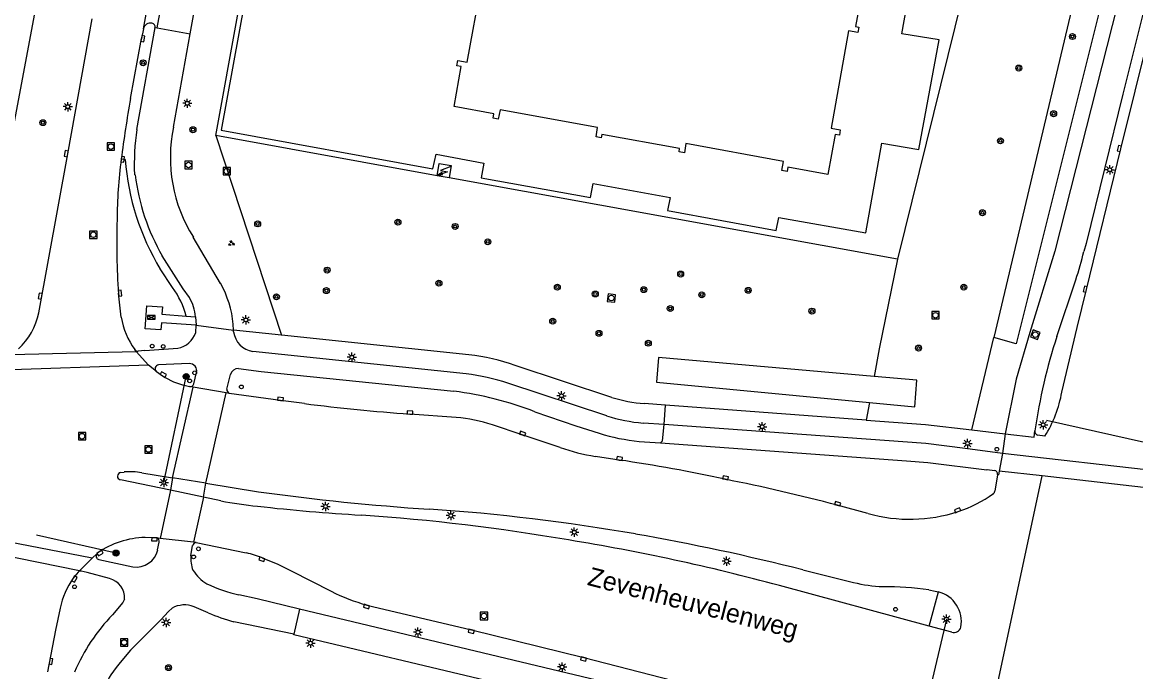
# Model space of a CAD drawing. Extents: x 130998 to 133001, y 398999 to 403002.
# Drawn here: x 132704.3 to 132854, y 399481.4 to 399568.7 of the extents above; entities that cross this region are included whole.
import ezdxf

# ---------------------------------------------------------------- set-up
doc = ezdxf.new("R2010")
doc.units = 0
for name, color, linetype in [('gg-afsc-hekwerk', 7, 'Continuous'), ('gg-anno-openbare ruimte label', 7, 'Continuous'), ('gg-bbg-hoofdgebouw', 7, 'Continuous'), ('gg-bbg-lage trafo', 7, 'Continuous'), ('gg-knt-verharding', 7, 'Continuous'), ('gg-knt-verharding nz', 7, 'Continuous'), ('gt-grn-groengrens', 7, 'Continuous'), ('gt-grn-weggrens', 7, 'Continuous'), ('gt-knt-lijn portaal', 7, 'Continuous'), ('gt-symb-boom', 7, 'Continuous'), ('gt-symb-drukknoppaal', 7, 'Continuous'), ('gt-symb-groenvak', 7, 'Continuous'), ('gt-symb-kolk', 7, 'Continuous'), ('gt-symb-lichtmast', 7, 'Continuous'), ('gt-symb-portaalmast', 7, 'Continuous'), ('gt-symb-rioolschacht', 7, 'Continuous'), ('gt-symb-trafo symbool', 7, 'Continuous'), ('gt-symb-verkeersregelinstallatiekast', 7, 'Continuous'), ('gt-symb-verkeersregelinstallatiepaal', 7, 'Continuous')]:
    doc.layers.add(name, color=color, linetype=linetype)

# ---------------------------------------------------------------- blocks, each defined once
blk = doc.blocks.new('gt0-KOLK')
at = {"layer": 'gt-symb-kolk'}
blk.add_lwpolyline([(0, 0), (0.37, 0), (0.37, 0.4), (-0.38, 0.4), (-0.38, 0), (0, 0)], dxfattribs=at)
blk = doc.blocks.new('gt0-VIPAAL')
at = {"layer": 'gt-symb-verkeersregelinstallatiepaal'}
blk.add_circle((0, 0), 0.25, dxfattribs=at)
blk = doc.blocks.new('gt0-PORTM')
at = {"layer": 'gt-symb-portaalmast'}
for radius in [0.4, 0.33, 0.27, 0.21, 0.15]:
    blk.add_circle((0, 0), radius, dxfattribs=at)
blk = doc.blocks.new('gt0-DPAAL')
at = {"layer": 'gt-symb-drukknoppaal'}
blk.add_circle((0, 0), 0.25, dxfattribs=at)
blk = doc.blocks.new('gt0-BOOM')
at = {"layer": 'gt-symb-boom'}
for radius in [0.4, 0.2]:
    blk.add_circle((0, 0), radius, dxfattribs=at)
blk = doc.blocks.new('gt0-LMAST')
at = {"layer": 'gt-symb-lichtmast'}
for p, q in [((-0.18, 0.17), (-0.45, 0.44)), ((-0.01, 0.25), (-0.01, 0.62)), ((0.17, 0.17), (0.44, 0.44)), ((-0.26, 0), (-0.63, 0)), ((-0.18, -0.18), (-0.45, -0.45)), ((-0.01, -0.25), (-0.01, -0.63)), ((0.44, -0.45), (0.17, -0.18)), ((0.24, 0), (0.62, 0))]:
    blk.add_line(p, q, dxfattribs=at)
blk.add_circle((-0.01, 0), 0.25, dxfattribs=at)
blk = doc.blocks.new('gt0-VRIKST')
at = {"layer": 'gt-symb-verkeersregelinstallatiekast'}
for p, q in [((-0.5, -0.25), (0.5, 0.25)), ((-0.5, 0.25), (0.5, -0.25))]:
    blk.add_line(p, q, dxfattribs=at)
blk.add_lwpolyline([(0.5, 0.25), (-0.5, 0.25), (-0.5, -0.25), (0.5, -0.25)], close=True, dxfattribs=at)
blk = doc.blocks.new('gt0-GRVAK')
at = {"layer": 'gt-symb-groenvak'}
for p, q in [((-0.11, 0.19), (-0.23, 0.24)), ((-0.18, 0.15), (0.09, 0.15)), ((-0.09, 0.21), (-0.16, 0.32)), ((-0.05, 0.21), (-0.05, 0.39)), ((0, 0.21), (0.06, 0.32)), ((0.01, 0.19), (0.13, 0.24)), ((0.26, -0.05), (0.2, 0.06)), ((0.3, -0.05), (0.3, 0.13)), ((0.35, -0.05), (0.41, 0.06)), ((-0.24, -0.23), (-0.36, -0.18)), ((-0.32, -0.26), (-0.05, -0.26)), ((-0.23, -0.21), (-0.29, -0.09)), ((-0.18, -0.2), (-0.18, -0.02)), ((-0.14, -0.21), (-0.07, -0.09)), ((-0.12, -0.23), (0, -0.18)), ((0.24, -0.07), (0.12, -0.02)), ((0.17, -0.11), (0.44, -0.11)), ((0.37, -0.07), (0.49, -0.02))]:
    blk.add_line(p, q, dxfattribs=at)
blk = doc.blocks.new('gt0-RS')
at = {"layer": 'gt-symb-rioolschacht'}
blk.add_lwpolyline([(-0.5, -0.5), (0.5, -0.5), (0.5, 0.5), (-0.5, 0.5)], close=True, dxfattribs=at)
blk.add_circle((0, 0), 0.375, dxfattribs=at)
blk = doc.blocks.new('gt0-HSP')
at = {"layer": 'gt-symb-trafo symbool'}
for points in [[(0.77, 0.75), (-0.53, 0), (0.47, 0), (-0.83, -0.75)], [(-0.22, -0.24), (-0.83, -0.75), (-0.08, -0.48)]]:
    blk.add_lwpolyline(points, dxfattribs=at)

msp = doc.modelspace()

# ---------------------------------------------------------------- linework, layer by layer
at = {"layer": 'gg-afsc-hekwerk'}
for p, q in [((132844.01, 399625.98), (132821.97, 399536.85)), ((132697.6, 399525.33), (132706.9, 399574.84)), ((132730.31, 399553.47), (132733.34, 399569.98)), ((132760.05, 399548.02), (132730.31, 399553.47)), ((132821.97, 399536.85), (132761.69, 399547.77))]:
    msp.add_line(p, q, dxfattribs=at)
at = {"layer": 'gg-bbg-hoofdgebouw'}
msp.add_lwpolyline([(132818.22, 399578.57), (132816.33, 399568.11), (132816.77, 399568.01), (132816.64, 399567.3), (132815.39, 399567.51), (132813.03, 399554.43), (132814.26, 399554.21), (132814.15, 399553.5), (132813.58, 399553.58), (132812.6, 399548.22), (132807.23, 399549.21), (132807.13, 399548.63), (132806.43, 399548.75), (132806.65, 399549.97), (132793.52, 399552.38), (132793.32, 399551.13), (132792.6, 399551.24), (132792.67, 399551.7), (132782.2, 399553.6), (132782.12, 399553.16), (132781.43, 399553.28), (132781.63, 399554.52), (132768.52, 399556.9), (132768.29, 399555.65), (132767.59, 399555.78), (132767.69, 399556.36), (132762.34, 399557.35), (132763.28, 399562.71), (132762.71, 399562.8), (132762.85, 399563.52), (132764.12, 399563.29), (132766.02, 399573.84)], dxfattribs=at)
at = {"layer": 'gg-bbg-lage trafo'}
msp.add_line((132761.69, 399547.77), (132760.05, 399548.02), dxfattribs=at)
msp.add_lwpolyline([(132760.05, 399548.02), (132760.32, 399549.68), (132761.96, 399549.41), (132761.69, 399547.77)], dxfattribs=at)
at = {"layer": 'gg-knt-verharding'}
for p, q in [((132720.58, 399567.79), (132724.07, 399586.98)), ((132722.42, 399567.92), (132725.76, 399586.22)), ((132726.88, 399567.12), (132727.67, 399571.55)), ((132719.69, 399554.27), (132722.14, 399567.96)), ((132720.58, 399567.79), (132720.31, 399566.5)), ((132722.14, 399567.96), (132722.42, 399567.92)), ((132718.83, 399558.43), (132720.31, 399566.5)), ((132724.64, 399554.56), (132726.88, 399567.12)), ((132719.47, 399548.18), (132719.37, 399548.2)), ((132730.96, 399533.58), (132727.29, 399539.79)), ((132843.4, 399526.44), (132845.92, 399534.07)), ((132717.58, 399529.02), (132717.22, 399532.24)), ((132726.34, 399529.16), (132727.57, 399529.08)), ((132727.57, 399529.08), (132727.65, 399527.95)), ((132727.62, 399526.98), (132727.65, 399527.95)), ((132732.69, 399527.28), (132732.65, 399528.08)), ((132739.15, 399526.61), (132732.69, 399527.28)), ((132732.71, 399527.06), (132732.69, 399527.28)), ((132764.34, 399523.96), (132739.15, 399526.61)), ((132720.76, 399524.54), (132719.86, 399524.47)), ((132720.76, 399524.54), (132725.19, 399524.86)), ((132763.98, 399521.41), (132735.27, 399524.43)), ((132726.72, 399522.79), (132722.62, 399522.62)), ((132783.54, 399518.25), (132770.56, 399522.55)), ((132722.32, 399521.74), (132723.16, 399521.16)), ((132727.35, 399520.06), (132727.72, 399521.58)), ((132731.8, 399519.37), (132732.27, 399521.33)), ((132726.25, 399519.85), (132726.79, 399519.7)), ((132782.86, 399515.77), (132769.59, 399520.17)), ((132790.77, 399517.2), (132787.92, 399517.41)), ((132817.75, 399515.19), (132790.77, 399517.2)), ((132762.63, 399515.56), (132756.41, 399516.01)), ((132817.75, 399515.19), (132825.74, 399514.61)), ((132790.57, 399514.61), (132787.77, 399514.79)), ((132825.74, 399514.61), (132831.96, 399513.88)), ((132831.96, 399513.88), (132836.43, 399513.35)), ((132836.43, 399513.35), (132836.08, 399510.69)), ((132787.24, 399512.34), (132790.08, 399512.13)), ((132841.77, 399513.04), (132840.79, 399513.15)), ((132836.08, 399510.69), (132831.07, 399511.36)), ((132836.08, 399510.69), (132835.64, 399508.35)), ((132784.56, 399509.83), (132781.35, 399510.32)), ((132717.5, 399508.16), (132717.99, 399508.22)), ((132720.36, 399508.11), (132724.48, 399507.44)), ((132724.48, 399507.44), (132724.2, 399505.79)), ((132835.4, 399507.86), (132835.04, 399505.65)), ((132724.2, 399505.79), (132717.48, 399507.18)), ((132728.64, 399504.83), (132728.96, 399506.7)), ((132728.96, 399506.7), (132736.06, 399505.57)), ((132730.99, 399504.35), (132728.64, 399504.83)), ((132817.99, 399502.64), (132813.87, 399503.75)), ((132722.49, 399497.76), (132722.71, 399498.79)), ((132727.69, 399498.73), (132734.41, 399497.34)), ((132726.96, 399496.96), (132727.2, 399498.32)), ((132714.6, 399496.44), (132719.15, 399495.48)), ((132711.82, 399494.77), (132711.14, 399493.93)), ((132809.24, 399495.07), (132816.05, 399493.37)), ((132826.21, 399487.49), (132806.1, 399492.96)), ((132826.21, 399487.49), (132827.45, 399492.12)), ((132729.29, 399489.29), (132727.39, 399490.09)), ((132741.56, 399489.79), (132740.82, 399486.41)), ((132792.11, 399477.72), (132741.56, 399489.79)), ((132740.82, 399486.41), (132732.74, 399488.1)), ((132829.25, 399486.69), (132826.21, 399487.49))]:
    msp.add_line(p, q, dxfattribs=at)
for points in [[(132901.43, 399740.52), (132890.59, 399708.5), (132889.85, 399706.06), (132889.16, 399703.6), (132885.94, 399691.45), (132873.35, 399642.43), (132865.28, 399610.8), (132857.35, 399579.47), (132852.24, 399559.02), (132847.33, 399538.95), (132847.01, 399537.87)], [(132869.85, 399643.31), (132858.59, 399599.11), (132850.82, 399568.23), (132843.11, 399537.92), (132839.74, 399526.96), (132837.9, 399520.68), (132836.43, 399513.35)], [(132844.07, 399518.96), (132846.11, 399527.65), (132847.38, 399532.75), (132851.98, 399551.67), (132857.77, 399574.97), (132861.41, 399589.44), (132866.24, 399608.29), (132874.84, 399642.05)], [(132734.18, 399571.34), (132731.05, 399554.17), (132759.51, 399548.97), (132759.93, 399550.94), (132766.33, 399549.73), (132765.98, 399547.78), (132780.7, 399545.1), (132781.03, 399546.99), (132791.38, 399545.11), (132791.03, 399543.38), (132805.64, 399540.69), (132806, 399542.45), (132817.69, 399540.35), (132819.86, 399552.42), (132824.83, 399551.56), (132827.55, 399566.29), (132822.54, 399567.14), (132824.39, 399577.39), (132830.94, 399576.21), (132833.57, 399590.79), (132827.01, 399592.03), (132829.12, 399603.48), (132837.22, 399602.02), (132842.25, 399629.36)], [(132706.51, 399529.62), (132710.4, 399550.98), (132713.71, 399569.15)], [(132726.76, 399531.67), (132725.94, 399532.83), (132723.11, 399537.28)], [(132727.65, 399527.95), (132723, 399528.29), (132722.92, 399527.31), (132720.81, 399527.45), (132721.02, 399530.55), (132723.14, 399530.41), (132723.06, 399529.42), (132726.34, 399529.16)], [(132733.36, 399522.12), (132736.43, 399521.73), (132762.32, 399519.08)], [(132742.22, 399517.42), (132739, 399517.82), (132732.12, 399518.79)], [(132773.22, 399516.32), (132778.72, 399514.41), (132781.86, 399513.42)], [(132776.59, 399511.51), (132771.5, 399513.2), (132767.49, 399514.54)], [(132790.08, 399512.13), (132790.38, 399512.41), (132790.57, 399514.61)], [(132831.07, 399511.36), (132825.75, 399512.03), (132790.57, 399514.61)], [(132790.08, 399512.13), (132823.16, 399509.74), (132826.06, 399509.51), (132833.98, 399508.51), (132834, 399508.57), (132835.01, 399508.43)], [(132835.64, 399508.35), (132835.55, 399507.85), (132835.4, 399507.86)], [(132722.33, 399499.35), (132722.06, 399499.37), (132720.8, 399499.42)], [(132714.41, 399497.33), (132714.36, 399497.29), (132714.31, 399497.23)], [(132736.56, 399496.69), (132738.65, 399495.82), (132740.46, 399494.94), (132745.81, 399492.19)], [(132716.04, 399493.89), (132713.03, 399494.73), (132712.23, 399494.89)], [(132718.05, 399491.14), (132717.83, 399490.7), (132716.44, 399489.04)], [(132741.56, 399489.79), (132735.89, 399491.19), (132733.42, 399491.71)], [(132826.16, 399492.37), (132827.01, 399492.22), (132827.45, 399492.12)], [(132709.4, 399489.92), (132708.75, 399486.97), (132707.7, 399481.36)], [(132724.43, 399489.91), (132723.95, 399489.47), (132722.91, 399488.35), (132718.84, 399484.27), (132717.45, 399482.63), (132716.91, 399481.95), (132716.21, 399480.97), (132715.97, 399480.58), (132715.62, 399479.84), (132715.24, 399478.88)], [(132750.63, 399490.33), (132764.7, 399487), (132779.79, 399483.29), (132794.75, 399479.44), (132808.74, 399475.76), (132812.85, 399474.65)], [(132767.55, 399479.99), (132740.8, 399486.33), (132740.82, 399486.41)]]:
    msp.add_lwpolyline(points, dxfattribs=at)
for centre, radius, start, end in [((132721.55, 399567.58), 0.992, 79.6332, 167.8621), ((132721.65, 399568.06), 0.497, 347.8024, 80.7236), ((132902.23, 399526.52), 186.15, 170.1311, 172.6692), ((132750.49, 399549.61), 31.14, 171.3902, 182.5961), ((132744.06, 399550.43), 19.86, 167.9729, 212.4033), ((132782.18, 399541.7), 65.15, 172.4405, 179.6426), ((132747.85, 399551.58), 28.58, 186.8446, 210.0379), ((132817.66, 399539.11), 100.67, 178.2926, 183.9131), ((132800.95, 399549.03), 47.4, 341.5976, 346.3803), ((132718.95, 399526.88), 13.75, 5.0182, 29.1755), ((132721.58, 399528.61), 6.02, 4.4418, 30.548), ((132697.54, 399531.47), 9.16, 312.9973, 348.3657), ((132728.16, 399530.97), 10.76, 190.408, 215.7017), ((132724.6, 399527.97), 3.17, 280.6759, 341.6658), ((132735.71, 399527.42), 3.02, 186.8065, 261.738), ((132916.41, 399502.63), 76.8, 161.9353, 171.6577), ((132719.87, 399525.03), 0.564, 217.7168, 268.943), ((132761.89, 399498.77), 25.31, 69.9685, 84.4437), ((132722.65, 399522.11), 0.506, 93.8371, 228.1277), ((132726.78, 399521.82), 0.97, 345.6842, 93.2707), ((132728.33, 399529.06), 9.45, 236.8087, 257.2387), ((132733.31, 399521.04), 1.08, 87.6142, 164.7419), ((132760.47, 399492.05), 29.56, 72.0242, 83.182), ((132726.86, 399520.21), 0.516, 261.8628, 342.5663), ((132732.34, 399519.29), 0.541, 170.8562, 245.8513), ((132756.58, 399473.5), 45.93, 68.76, 82.8215), ((132789.49, 399537.49), 20.14, 252.8133, 265.5292), ((132827.38, 399522.03), 16.96, 338.793, 349.5634), ((132775.14, 399777.06), 261.72, 262.7749, 265.8959), ((132760.78, 399494.69), 20.96, 71.3237, 84.9441), ((132789.88, 399538.24), 23.54, 252.6376, 264.8636), ((132827.38, 399522.01), 16.96, 328.0877, 338.8627), ((132789.86, 399539.17), 26.96, 252.7255, 264.409), ((132841.03, 399513.7), 0.601, 173.8714, 246.3979), ((132785.81, 399538.37), 28.4, 251.0514, 260.9724), ((132754.48, 399304.02), 208, 77.6998, 81.6848), ((132717.59, 399507.66), 0.502, 100.5491, 256.5342), ((132718.76, 399499.62), 8.64, 79.3806, 95.1529), ((132834.93, 399507.95), 0.486, 350.1383, 80.0644), ((132751.3, 399267.65), 244.25, 75.1565, 78.7877), ((132780.08, 399823.82), 321.29, 262.124, 266.2368), ((132824.29, 399520.1), 18.16, 288.7308, 305.5385), ((132834.64, 399505.66), 0.393, 300.542, 359.1169), ((132742.6, 399565.93), 62.67, 259.3234, 263.8907), ((132765.19, 399764.27), 262.29, 263.5963, 266.6563), ((132740.31, 399231.68), 272.2, 80.1799, 86.0635), ((132823.63, 399522.71), 20.84, 254.3095, 288.1466), ((132730.84, 399225.81), 277.27, 80.2681, 86.0607), ((132733.65, 399196.61), 307.88, 75.7866, 80.0715), ((132721.07, 399487.77), 11.65, 91.2863, 124.8291), ((132722.22, 399498.86), 0.501, 351.9297, 77.5032), ((132727.67, 399498.25), 0.475, 87.1196, 172.1255), ((132733.76, 399226.96), 275.65, 74.7878, 80.8262), ((132714.71, 399496.93), 0.498, 142.7091, 257.187), ((132719.62, 399498.39), 2.95, 260.8133, 347.5956), ((132730.98, 399496.55), 4.04, 174.2479, 202.1621), ((132730.28, 399479.7), 18.12, 69.7064, 76.8021), ((132719.81, 399487.79), 10.63, 144.7121, 168.4465), ((132712.15, 399494.41), 0.482, 79.8466, 132.9924), ((132715.4, 399491.32), 2.65, 356.1407, 76.1214), ((132732.28, 399498.21), 5.96, 212.2722, 237.7278), ((132739.7, 399517.4), 26.45, 246.3684, 256.2694), ((132820.88, 399512.82), 20.03, 256.0382, 267.5114), ((132820.39, 399453.82), 38.98, 81.4932, 90.5569), ((132758.3, 399517.36), 28.1, 243.6116, 254.154), ((132826.37, 399488.08), 4.18, 350.0852, 75.0425), ((132726.09, 399487.03), 3.32, 67.0665, 119.9872), ((132735.01, 399471.18), 25.77, 136.1165, 156.7921), ((132739.59, 399513.56), 26.37, 247.0096, 254.9495), ((132829.55, 399487.62), 0.977, 252.4702, 344.6662)]:
    msp.add_arc(centre, radius, start, end, dxfattribs=at)
at = {"layer": 'gg-knt-verharding nz'}
for p, q in [((132702.76, 399524.02), (132719.59, 399524.43)), ((132719.59, 399524.43), (132719.43, 399524.69)), ((132721.26, 399522.58), (132719.59, 399524.43)), ((132722.32, 399521.74), (132721.26, 399522.58)), ((132724.48, 399507.44), (132727.25, 399519.62)), ((132727.25, 399519.62), (132726.79, 399519.7)), ((132731.69, 399518.87), (132727.25, 399519.62)), ((132728.96, 399506.7), (132731.69, 399518.87)), ((132732.12, 399518.79), (132731.69, 399518.87)), ((132857.61, 399508.28), (132836.08, 399510.69)), ((132728.96, 399506.7), (132724.48, 399507.44)), ((132841.4, 399507.69), (132835.64, 399508.35)), ((132857.86, 399505.8), (132841.4, 399507.69)), ((132724.2, 399505.79), (132722.82, 399499.29)), ((132728.64, 399504.83), (132724.2, 399505.79)), ((132728.64, 399504.83), (132727.3, 399498.77)), ((132713.69, 399496.62), (132700.92, 399499.12)), ((132722.82, 399499.29), (132722.33, 399499.35)), ((132727.3, 399498.77), (132722.82, 399499.29)), ((132727.69, 399498.73), (132727.3, 399498.77)), ((132711.99, 399494.93), (132700.57, 399497.25)), ((132714.31, 399497.23), (132713.69, 399496.62)), ((132713.69, 399496.62), (132711.99, 399494.93)), ((132711.99, 399494.93), (132711.82, 399494.77))]:
    msp.add_line(p, q, dxfattribs=at)
msp.add_lwpolyline([(132721.26, 399522.58), (132700.2, 399521.88), (132699.24, 399522.05)], dxfattribs=at)
at = {"layer": 'gt-grn-groengrens'}
for p, q in [((132730.31, 399553.47), (132739.15, 399526.61)), ((132718.13, 399550.23), (132717.6, 399550.27)), ((132724.51, 399533.02), (132722.83, 399535.51)), ((132831.96, 399513.88), (132834.91, 399526.3)), ((132818.19, 399517.55), (132817.75, 399515.19))]:
    msp.add_line(p, q, dxfattribs=at)
for points in [[(132889.34, 399742.98), (132850.51, 399592.1), (132834.91, 399526.3)], [(132867.67, 399643.86), (132854.6, 399592.15), (132837.93, 399525.45), (132834.91, 399526.3)], [(132821.97, 399536.85), (132819.51, 399524.77), (132818.82, 399521.06)], [(132818.82, 399521.06), (132789.85, 399523.59), (132789.58, 399520.28), (132818.19, 399517.55)], [(132818.19, 399517.55), (132824.29, 399516.97), (132824.57, 399520.55), (132818.82, 399521.06)]]:
    msp.add_lwpolyline(points, dxfattribs=at)
for centre, radius, start, end in [((132751.66, 399552.84), 33.64, 184.4477, 211.0157), ((132715.03, 399526.16), 11.7, 14.8716, 35.8655)]:
    msp.add_arc(centre, radius, start, end, dxfattribs=at)
at = {"layer": 'gt-grn-weggrens'}
for p, q in [((132722.42, 399567.92), (132726.88, 399567.12)), ((132727.65, 399527.95), (132732.69, 399527.28)), ((132790.57, 399514.61), (132790.77, 399517.2)), ((132831.72, 399462.47), (132841.4, 399507.69))]:
    msp.add_line(p, q, dxfattribs=at)
msp.add_lwpolyline([(132836.43, 399513.35), (132840.33, 399512.92), (132840.43, 399513.77)], dxfattribs=at)
at = {"layer": 'gt-knt-lijn portaal'}
for p, q in [((132723.32, 399506.82), (132726.33, 399521.06)), ((132842, 399515.18), (132859.33, 399511.28)), ((132716.9, 399497.33), (132706.22, 399499.74)), ((132828.54, 399488.43), (132823.16, 399465.61))]:
    msp.add_line(p, q, dxfattribs=at)

# ---------------------------------------------------------------- block references
at = {"layer": 'gt-symb-boom'}
for p in [(132845.48, 399566.75), (132720.54, 399563.23), (132838.27, 399562.52), (132842.95, 399556.38), (132707.06, 399555.18), (132727.24, 399554.23), (132835.8, 399552.74), (132833.38, 399543.07), (132735.94, 399541.57), (132754.8, 399541.81), (132762.48, 399541.23), (132766.88, 399539.16), (132745.28, 399535.36), (132792.81, 399534.83), (132745.18, 399532.6), (132760.31, 399533.61), (132776.23, 399533.07), (132787.85, 399532.73), (132801.89, 399532.64), (132830.87, 399533.07), (132738.46, 399531.77), (132781.33, 399532.15), (132795.65, 399532.03), (132791.41, 399530.19), (132810.46, 399529.85), (132775.61, 399528.5), (132781.83, 399526.86), (132788.46, 399525.53), (132824.79, 399524.88), (132723.96, 399481.92)]:
    msp.add_blockref('gt0-BOOM', p, dxfattribs=at)
at = {"layer": 'gt-symb-drukknoppaal'}
for p in [(132723.24, 399525.1), (132727.47, 399521.55), (132835.33, 399511.28), (132727.33, 399496.81)]:
    msp.add_blockref('gt0-DPAAL', p, dxfattribs=at)
at = {"layer": 'gt-symb-groenvak', "rotation": -10.30997039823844}
msp.add_blockref('gt0-GRVAK', (132732.39, 399538.94), dxfattribs=at)
at = {"layer": 'gt-symb-kolk'}
for p, rotation in [((132720.31, 399566.5), -100.38568294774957), ((132710.4, 399550.98), 79.65545752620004), ((132851.98, 399551.67), 76.0609856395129), ((132717.6, 399550.27), -95.941846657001), ((132847.38, 399532.75), 76.29711003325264), ((132706.91, 399531.84), 79.68721352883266), ((132717.22, 399532.24), -83.6277257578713), ((132723.16, 399521.16), -28.456529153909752), ((132739, 399517.82), -7.185074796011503), ((132756.41, 399516.01), -4.135059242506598), ((132771.5, 399513.2), -18.340523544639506), ((132784.56, 399509.83), -9.337616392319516), ((132798.79, 399507.24), -12.155063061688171), ((132813.87, 399503.75), -15.14611614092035), ((132830.12, 399502.9), 23.138193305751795), ((132722.06, 399499.37), 178.0306279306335), ((132714.64, 399497.47), -149.34624659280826), ((132736.56, 399496.69), 160.98833601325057), ((132711.14, 399493.93), -120.01013764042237), ((132750.63, 399490.33), 161.93252307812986), ((132764.7, 399487), 166.69386138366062), ((132707.96, 399482.8), -100.40301367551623), ((132779.79, 399483.29), 166.18882846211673)]:
    msp.add_blockref('gt0-KOLK', p, dxfattribs=dict(at, rotation=rotation))
at = {"layer": 'gt-symb-lichtmast'}
for p in [(132726.49, 399557.78), (132710.41, 399557.33), (132850.5, 399548.85), (132734.37, 399528.66), (132748.6, 399523.65), (132776.8, 399518.47), (132803.78, 399514.31), (132841.54, 399514.57), (132831.39, 399512.06), (132723.32, 399506.82), (132745.08, 399503.59), (132761.92, 399502.37), (132778.52, 399500.13), (132799, 399496.23), (132723.66, 399487.99), (132828.54, 399488.43), (132757.5, 399486.68), (132743.04, 399485.21), (132776.87, 399482.01)]:
    msp.add_blockref('gt0-LMAST', p, dxfattribs=at)
at = {"layer": 'gt-symb-portaalmast'}
for p in [(132726.33, 399521.06), (132716.9, 399497.33)]:
    msp.add_blockref('gt0-PORTM', p, dxfattribs=at)
at = {"layer": 'gt-symb-rioolschacht'}
for p in [(132716.21, 399551.96), (132726.65, 399549.49), (132731.78, 399548.65), (132713.85, 399540.11), (132827.07, 399529.29), (132712.33, 399513.03), (132721.27, 399511.24), (132766.37, 399488.87), (132718, 399485.3)]:
    msp.add_blockref('gt0-RS', p, dxfattribs=at)
for p, rotation in [((132783.49, 399531.6), -95.73909849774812), ((132840.49, 399526.68), 68.53893641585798)]:
    msp.add_blockref('gt0-RS', p, dxfattribs=dict(at, rotation=rotation))
at = {"layer": 'gt-symb-trafo symbool', "rotation": -10.30997039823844}
msp.add_blockref('gt0-HSP', (132761.02, 399548.67), dxfattribs=at)
at = {"layer": 'gt-symb-verkeersregelinstallatiekast'}
msp.add_blockref('gt0-VRIKST', (132721.65, 399529.02), dxfattribs=at)
at = {"layer": 'gt-symb-verkeersregelinstallatiepaal'}
for p in [(132721.76, 399525.15), (132726.8, 399520.46), (132733.75, 399519.66), (132727.97, 399497.89), (132711.33, 399492.79), (132821.7, 399489.76)]:
    msp.add_blockref('gt0-VIPAAL', p, dxfattribs=at)

# ---------------------------------------------------------------- texts
at = {"layer": 'gg-anno-openbare ruimte label'}
msp.add_text('Zevenheuvelenweg', height=2.5, rotation=345.5, dxfattribs=at).set_placement((132780.14, 399493.06))

doc.saveas('drawing.dxf')
